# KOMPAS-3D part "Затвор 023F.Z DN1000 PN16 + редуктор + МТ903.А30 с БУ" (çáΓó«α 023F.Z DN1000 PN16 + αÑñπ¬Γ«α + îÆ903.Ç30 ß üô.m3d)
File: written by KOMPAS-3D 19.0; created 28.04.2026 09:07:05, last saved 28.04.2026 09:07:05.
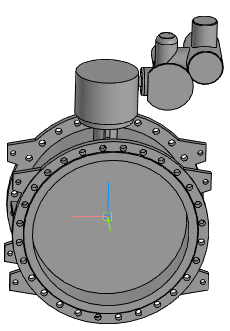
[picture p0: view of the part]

Document properties: Полное имя файла: ..\..\Затвор 023F.Z DN400-DN1600 + редуктор + МТ903\Затвор 023F.Z DN1000 PN16 + редуктор + МТ903.А30 с БУ.a3d

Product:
- Part/product: Затвор 023F.Z DN1000 PN16 + редуктор + МТ903.А30 с БУ
    Масса: 1887.38

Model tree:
1. Операция без истории:1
